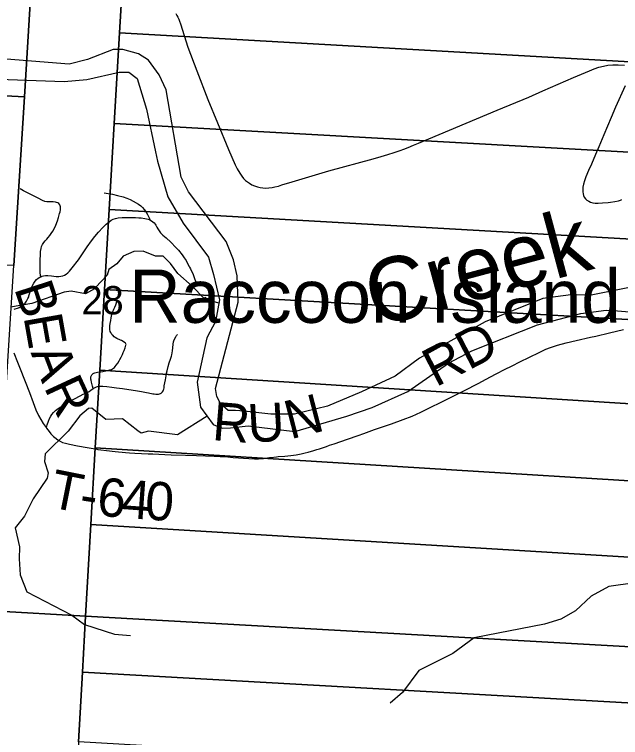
# Model space of a CAD drawing. Extents: x 396.2 to 468.4, y 232.6 to 279.1.
# Drawn here: x 422.748 to 423.645, y 273.001 to 274.071 of the extents above; entities that cross this region are included whole.
import ezdxf

# ---------------------------------------------------------------- set-up
doc = ezdxf.new("R2010")
doc.units = 0
for name, color, linetype in [('GM_X_County_Road', 7, 'Continuous'), ('GM_X_Major_River', 7, 'Continuous'), ('GM_X_Major_River_Text', 7, 'Continuous'), ('GM_X_Minor_River', 7, 'Continuous'), ('GM_X_Section', 7, 'Continuous'), ('GM_X_Section_Text', 7, 'Continuous'), ('GM_X_Township_Road', 7, 'Continuous'), ('GM_X_Township_Road_Text', 7, 'Continuous'), ('GM_X_Unincorporated_Text', 7, 'Continuous')]:
    doc.layers.add(name, color=color, linetype=linetype)

msp = doc.modelspace()

# ---------------------------------------------------------------- linework, layer by layer
at = {"layer": 'GM_X_County_Road'}
msp.add_lwpolyline([(422.9868, 274.0726), (422.9883, 274.0699), (422.9898, 274.0671), (422.991, 274.0645), (422.9922, 274.0614), (422.9935, 274.0576), (423.0046, 274.0229), (423.0175, 273.988), (423.0341, 273.9452), (423.0483, 273.9108), (423.0646, 273.8713), (423.0746, 273.8486), (423.0776, 273.8429), (423.0814, 273.8364), (423.0843, 273.8318), (423.0869, 273.8284), (423.0899, 273.8254), (423.0926, 273.8233), (423.0956, 273.8213), (423.0992, 273.8192), (423.103, 273.8176), (423.1073, 273.8161), (423.1113, 273.8151), (423.1156, 273.8144), (423.1199, 273.8142), (423.1243, 273.8144), (423.129, 273.8151), (423.1334, 273.816), (423.1385, 273.8173), (423.1436, 273.8189), (423.159, 273.8236), (423.213, 273.8396), (423.2788, 273.8574), (423.2907, 273.8608), (423.3004, 273.8638), (423.3098, 273.8668), (423.3189, 273.87), (423.3244, 273.872), (423.3306, 273.8744), (423.3387, 273.8776), (423.3461, 273.8808), (423.4622, 273.9297), (423.5091, 273.949), (423.5301, 273.9582), (423.5751, 273.9779), (423.5992, 273.9881), (423.606, 273.9909), (423.6127, 273.9933), (423.6195, 273.995), (423.6263, 273.9961), (423.6336, 273.9966), (423.6416, 273.9967), (423.651, 273.9965)], dxfattribs=at)
at = {"layer": 'GM_X_Major_River'}
for p, q in [((423.6015, 273.6556), (423.5712, 273.6562)), ((423.0513, 273.6489), (423.0454, 273.6166))]:
    msp.add_line(p, q, dxfattribs=at)
for points in [[(422.599, 274.13), (422.5858, 274.0582), (422.5866, 274.0453), (422.5951, 274.0176), (422.608, 274.0044), (422.6671, 273.9809), (422.6966, 273.9765), (422.8215, 273.9719)], [(423.5712, 273.6562), (423.53, 273.6506), (423.4444, 273.616), (423.3475, 273.5623), (423.3113, 273.5359), (423.2615, 273.5125), (423.2113, 273.4913), (423.1622, 273.4796), (423.1275, 273.4794), (423.0877, 273.4841), (423.0752, 273.4848), (423.0639, 273.4851), (423.0533, 273.4942), (423.0471, 273.5055), (423.0456, 273.5176), (423.0789, 273.6453), (423.0776, 273.6844), (423.0721, 273.7082), (423.061, 273.7351), (423.0054, 273.8088), (422.9947, 273.8303), (422.9721, 273.9595), (422.9621, 273.9819), (422.9461, 274.0038), (422.9313, 274.0128), (422.9082, 274.0195), (422.8938, 274.0194), (422.8557, 274.0048), (422.8285, 273.9978), (422.7358, 274.0052)], [(422.8215, 273.9719), (422.8551, 273.9748), (422.9027, 273.9857), (422.9171, 273.9858), (422.9296, 273.9767), (422.9431, 273.9309), (422.9563, 273.868), (422.9594, 273.854), (422.9748, 273.8014), (422.9977, 273.7624), (423.0351, 273.7118), (423.0424, 273.6861), (423.0513, 273.6489)], [(424.0857, 273.9753), (424.0692, 273.9475), (424.0531, 273.9265), (424.0445, 273.8995), (424.0269, 273.8084), (424.0187, 273.7856), (424.0044, 273.7616), (423.9626, 273.7332), (423.9158, 273.7178), (423.8274, 273.7028), (423.7817, 273.6916), (423.6015, 273.6556)], [(423.0454, 273.6166), (423.0323, 273.5927), (423.0183, 273.527), (423.023, 273.4898), (423.0421, 273.4641), (423.055, 273.4589), (423.0678, 273.4593), (423.0935, 273.4622), (423.1628, 273.4538), (423.2398, 273.4763), (423.2772, 273.4894), (423.33, 273.5132), (423.3903, 273.555), (423.4246, 273.573), (423.5219, 273.6119), (423.5861, 273.6286), (423.6239, 273.6333), (423.6345, 273.633), (423.6584, 273.6309)]]:
    msp.add_lwpolyline(points, dxfattribs=at)
at = {"layer": 'GM_X_Minor_River'}
for points in [[(423.0503, 273.6438), (423.0338, 273.6486), (423.0304, 273.6524), (423.0285, 273.6505), (423.0107, 273.669), (422.9895, 273.6876), (422.9786, 273.7028), (422.968, 273.7134), (422.9566, 273.7134), (422.9381, 273.721), (422.9245, 273.7205), (422.9086, 273.7133), (422.8992, 273.7022), (422.8875, 273.6935), (422.8852, 273.6851), (422.8678, 273.6668), (422.8663, 273.6649), (422.8527, 273.6577), (422.8319, 273.6614), (422.8213, 273.6599), (422.7734, 273.6434), (422.742, 273.638)], [(423.0329, 273.4764), (422.989, 273.4489), (422.9461, 273.4541), (422.9354, 273.4514), (422.9302, 273.4546), (422.9077, 273.4724), (422.8828, 273.4717), (422.8625, 273.4883), (422.8575, 273.4877), (422.8444, 273.4771), (422.8271, 273.4545), (422.7931, 273.4206), (422.7924, 273.4096), (422.7976, 273.3924), (422.7962, 273.3848), (422.7756, 273.3543), (422.7732, 273.3491), (422.7628, 273.3286), (422.7486, 273.3112), (422.755, 273.2832), (422.7548, 273.2654), (422.756, 273.2414), (422.7662, 273.2164), (422.8328, 273.182), (422.8516, 273.1681), (422.8958, 273.1538), (422.9195, 273.1515)], [(423.6662, 273.2298), (423.6278, 273.2242), (423.6013, 273.2099), (423.5784, 273.1882), (423.5568, 273.176), (423.5324, 273.1684), (423.4282, 273.1482), (423.3965, 273.1249), (423.3462, 273.0999), (423.3222, 273.0673), (423.304, 273.0515)]]:
    msp.add_lwpolyline(points, dxfattribs=at)
at = {"layer": 'GM_X_Section'}
for points in [[(422.7773, 274.1944), (422.7625, 273.9495), (421.7308, 274.0039), (421.7452, 274.2485)], [(422.7773, 274.1944), (422.9116, 274.1851), (422.9033, 274.0442), (422.8955, 273.9099), (422.888, 273.7823), (422.8811, 273.6643), (422.8741, 273.5445), (422.8674, 273.4297), (422.8607, 273.3162), (422.8528, 273.1802), (422.7149, 273.188), (422.7307, 273.4397), (422.7469, 273.6994), (422.7625, 273.9495)], [(422.9116, 274.1851), (423.8062, 274.1333), (423.7981, 273.9932), (422.9033, 274.0442)], [(423.7981, 273.9932), (423.7904, 273.8602), (422.8955, 273.9099), (422.9033, 274.0442)], [(421.7308, 274.0039), (422.7625, 273.9495), (422.7469, 273.6994), (421.7144, 273.7468)], [(422.8955, 273.9099), (423.7904, 273.8602), (423.7829, 273.7317), (422.888, 273.7823)], [(423.7829, 273.7317), (423.776, 273.6125), (422.8811, 273.6643), (422.888, 273.7823)], [(422.8811, 273.6643), (423.776, 273.6125), (423.7688, 273.4879), (422.8741, 273.5445)], [(423.7688, 273.4879), (423.7622, 273.3741), (422.8674, 273.4297), (422.8741, 273.5445)], [(422.8674, 273.4297), (423.7622, 273.3741), (423.7556, 273.2617), (422.8607, 273.3162)], [(423.7556, 273.2617), (423.748, 273.13), (422.8528, 273.1802), (422.8607, 273.3162)], [(422.8528, 273.1802), (422.8483, 273.0976), (422.8427, 272.9941), (422.8371, 272.89), (422.8314, 272.7848), (422.8262, 272.6889), (422.8208, 272.5886), (422.8152, 272.4837), (422.8095, 272.3782), (422.8042, 272.2802), (422.7982, 272.1692), (422.6516, 272.1773), (422.6675, 272.4285), (422.6838, 272.6898), (422.6989, 272.9313), (422.7149, 273.188)], [(423.748, 273.13), (423.7432, 273.047), (422.8483, 273.0976), (422.8528, 273.1802)], [(423.7432, 273.047), (423.7371, 272.9426), (422.8427, 272.9941), (422.8483, 273.0976)]]:
    msp.add_lwpolyline(points, close=True, dxfattribs=at)
at = {"layer": 'GM_X_Township_Road'}
for points in [[(423.6516, 273.9658), (423.6377, 273.9343), (423.6312, 273.9189), (423.6204, 273.8933), (423.613, 273.8755), (423.608, 273.8641), (423.6018, 273.8499), (423.5975, 273.8403), (423.5938, 273.831), (423.5917, 273.8252), (423.5901, 273.8198), (423.5892, 273.8155), (423.5889, 273.8118), (423.5889, 273.8087), (423.5894, 273.8056), (423.5901, 273.8033), (423.5911, 273.801), (423.5929, 273.7985), (423.5952, 273.7964), (423.5978, 273.7948), (423.6007, 273.7935), (423.6037, 273.7926), (423.6073, 273.7921), (423.6117, 273.7919), (423.6185, 273.7923), (423.6266, 273.7931), (423.6303, 273.7935), (423.6364, 273.7943), (423.6419, 273.7954), (423.6448, 273.7964), (423.647, 273.7975)], [(422.7867, 273.683), (422.786, 273.6884), (422.7856, 273.695), (422.7856, 273.7031), (422.7865, 273.7205), (422.7871, 273.7248), (422.7879, 273.7277), (422.7892, 273.7306), (422.7912, 273.7337), (422.7931, 273.736), (422.7955, 273.7387), (422.7978, 273.7412), (422.8002, 273.7441), (422.8021, 273.7468), (422.8044, 273.7502), (422.8063, 273.754), (422.8088, 273.7592), (422.8113, 273.7658), (422.8131, 273.7707), (422.8146, 273.7765), (422.8152, 273.7791), (422.8159, 273.7821), (422.8161, 273.7846), (422.816, 273.7865), (422.8154, 273.7882), (422.8149, 273.7893), (422.8133, 273.7912), (422.8118, 273.7922), (422.8101, 273.793), (422.8083, 273.7934), (422.8052, 273.7937), (422.8023, 273.7937), (422.7989, 273.7937), (422.7958, 273.794), (422.7928, 273.7946), (422.7893, 273.7959), (422.7826, 273.7992), (422.771, 273.8051), (422.7611, 273.8104), (422.756, 273.8129)], [(422.8804, 273.8071), (422.8835, 273.8067), (422.8927, 273.805), (422.9005, 273.8033), (422.9089, 273.8012), (422.9143, 273.7995), (422.9188, 273.7975), (422.9237, 273.7949), (422.9312, 273.7904), (422.9348, 273.7879), (422.9375, 273.7854), (422.9399, 273.7826), (422.9421, 273.7796), (422.9445, 273.7753), (422.9463, 273.772), (422.9475, 273.7692), (422.9483, 273.7671)], [(422.7471, 273.6349), (422.7538, 273.6369), (422.7549, 273.6373), (422.7574, 273.6389), (422.7584, 273.6395), (422.7603, 273.6411), (422.7621, 273.6427), (422.7634, 273.644), (422.7656, 273.6469), (422.7662, 273.6479), (422.7676, 273.6506), (422.7688, 273.6534), (422.7692, 273.6546), (422.7701, 273.6575), (422.7716, 273.6622), (422.7731, 273.6668), (422.7746, 273.6702), (422.7763, 273.6733), (422.7783, 273.6764), (422.7804, 273.6787), (422.7827, 273.6807), (422.7853, 273.6823), (422.7867, 273.683), (422.7881, 273.6837), (422.7905, 273.6844), (422.7935, 273.6849), (422.7973, 273.6849), (422.8028, 273.6843), (422.8095, 273.6835), (422.8132, 273.6834), (422.8163, 273.6837), (422.8193, 273.6844), (422.8216, 273.6853), (422.8243, 273.6869), (422.8267, 273.6888), (422.8294, 273.6914), (422.8334, 273.6962), (422.8425, 273.7079), (422.8467, 273.714), (422.8552, 273.727), (422.8616, 273.7361), (422.8666, 273.7425), (422.8722, 273.7491), (422.8786, 273.7559), (422.8834, 273.7607), (422.8874, 273.764), (422.8909, 273.7667), (422.8939, 273.7681), (422.8973, 273.7692), (422.9011, 273.77), (422.907, 273.7705), (422.9146, 273.7706), (422.9216, 273.7706), (422.927, 273.7707), (422.9319, 273.7704), (422.9355, 273.77), (422.9409, 273.7691), (422.9457, 273.768), (422.9483, 273.7671), (422.9508, 273.7659), (422.9528, 273.7645), (422.9545, 273.7627), (422.9559, 273.7609), (422.9569, 273.7591), (422.9583, 273.7566), (422.9599, 273.7539), (422.9618, 273.7511), (422.9641, 273.7482), (422.9675, 273.7446), (422.9721, 273.7404), (422.979, 273.7342), (422.9868, 273.7264), (422.9908, 273.7221), (422.996, 273.7152), (422.999, 273.7111), (423.0017, 273.707), (423.0035, 273.7037), (423.0066, 273.6983), (423.0071, 273.6973), (423.0084, 273.6947), (423.0121, 273.6865), (423.0139, 273.6817), (423.0162, 273.6751)], [(422.8645, 273.5175), (422.8635, 273.5208), (422.8618, 273.5267), (422.8612, 273.5297), (422.8609, 273.5315), (422.8607, 273.5326), (422.8607, 273.5338), (422.8608, 273.5348), (422.8611, 273.5357), (422.8616, 273.5368), (422.8623, 273.5376), (422.8629, 273.5383), (422.8636, 273.539), (422.8645, 273.5397), (422.8654, 273.5402), (422.8666, 273.5407), (422.8686, 273.5411), (422.8705, 273.5414), (422.8737, 273.5419), (422.8786, 273.5426), (422.8829, 273.5435), (422.886, 273.5441), (422.8888, 273.5449), (422.8912, 273.5458), (422.893, 273.5467), (422.8942, 273.5474), (422.8956, 273.5485), (422.8969, 273.5499), (422.8985, 273.5519), (422.9008, 273.5551), (422.9026, 273.5582), (422.9039, 273.5605), (422.9056, 273.564), (422.9075, 273.5677), (422.9089, 273.5706), (422.9102, 273.5738), (422.9118, 273.5779), (422.9123, 273.5796), (422.9128, 273.5818), (422.9129, 273.5827), (422.9126, 273.5836), (422.912, 273.5845), (422.9107, 273.5857), (422.9086, 273.5871), (422.9064, 273.5883), (422.9047, 273.589), (422.9025, 273.59), (422.9014, 273.5905), (422.8993, 273.5916), (422.8969, 273.5932), (422.8954, 273.5942), (422.8932, 273.5962), (422.8924, 273.5971), (422.8917, 273.5979), (422.891, 273.5989), (422.8902, 273.6004), (422.8896, 273.6019), (422.8889, 273.6047), (422.8889, 273.607), (422.8891, 273.6101), (422.8896, 273.6138), (422.8902, 273.6181), (422.8909, 273.6223), (422.892, 273.6269), (422.8933, 273.6308), (422.8948, 273.6347), (422.8962, 273.6381), (422.8978, 273.6415), (422.8989, 273.6444), (422.8995, 273.6467), (422.8998, 273.6479)], [(422.8696, 273.4275), (422.8713, 273.4273), (422.8756, 273.4267), (422.8842, 273.4256), (422.897, 273.4242), (422.9121, 273.4228), (422.9181, 273.4224), (422.9259, 273.4219), (422.9456, 273.4209), (422.9524, 273.4206), (422.9617, 273.4202), (422.9704, 273.4198), (422.9796, 273.4193), (423.0007, 273.4185), (423.0174, 273.4181), (423.0432, 273.4173), (423.0524, 273.4169), (423.0634, 273.4161), (423.0714, 273.4154), (423.0794, 273.4147), (423.0868, 273.4141), (423.0949, 273.4136), (423.1029, 273.4133), (423.109, 273.4134), (423.1163, 273.414), (423.1251, 273.4152), (423.1274, 273.4155), (423.1358, 273.4165), (423.1382, 273.4167), (423.1481, 273.4175), (423.1524, 273.4178), (423.1567, 273.4183), (423.1647, 273.419), (423.172, 273.4205), (423.178, 273.422), (423.1826, 273.4232), (423.1911, 273.4257), (423.1955, 273.427), (423.1994, 273.4283), (423.2039, 273.4297), (423.2096, 273.4316), (423.2141, 273.4333), (423.2211, 273.4356), (423.241, 273.4422), (423.2568, 273.448), (423.2649, 273.451), (423.2808, 273.4567), (423.3059, 273.4652), (423.3234, 273.4714), (423.3367, 273.4767), (423.3492, 273.4823), (423.3652, 273.4902), (423.3776, 273.4963), (423.3865, 273.5006), (423.4131, 273.5141), (423.4351, 273.5256), (423.445, 273.5307), (423.4609, 273.5393), (423.4742, 273.546), (423.4837, 273.5506), (423.497, 273.5573), (423.5093, 273.5634), (423.5254, 273.5715), (423.5344, 273.5756), (423.5414, 273.5782), (423.5514, 273.5815), (423.5646, 273.5852), (423.5791, 273.5887), (423.6003, 273.5933), (423.6082, 273.5951), (423.6287, 273.6001), (423.6493, 273.6048)], [(422.7946, 273.4595), (422.7958, 273.4615), (422.7964, 273.4637), (422.7981, 273.469), (422.7998, 273.473), (422.8014, 273.4763), (422.8031, 273.4789), (422.8054, 273.4818), (422.8085, 273.4849), (422.8123, 273.488), (422.8202, 273.493), (422.8287, 273.4981), (422.8365, 273.5022), (422.8452, 273.5067), (422.8496, 273.5089), (422.8542, 273.5109), (422.8584, 273.5132), (422.8608, 273.515), (422.8645, 273.5175), (422.867, 273.5191), (422.8693, 273.52), (422.8723, 273.5208), (422.8746, 273.521), (422.8787, 273.5209), (422.8843, 273.5204), (422.8917, 273.5195), (422.899, 273.5185), (422.9076, 273.5173), (422.9107, 273.5169), (422.9205, 273.5154), (422.9297, 273.514), (422.9358, 273.513), (422.9431, 273.5117), (422.946, 273.511), (422.9528, 273.5097), (422.9545, 273.5094), (422.9572, 273.509), (422.9587, 273.5089), (422.9603, 273.509), (422.9612, 273.5091), (422.9626, 273.5094), (422.9639, 273.51), (422.9649, 273.5106), (422.9661, 273.5115), (422.9671, 273.5127), (422.9678, 273.5139), (422.9683, 273.5153), (422.9687, 273.5163), (422.9692, 273.5184), (422.9696, 273.5213), (422.9711, 273.5301), (422.9716, 273.5331), (422.9722, 273.536), (422.973, 273.5401), (422.9738, 273.5436), (422.9754, 273.5501), (422.977, 273.5555), (422.9788, 273.5607), (422.9804, 273.5653), (422.9808, 273.5671), (422.9819, 273.573), (422.9823, 273.5778), (422.9827, 273.5832), (422.9834, 273.5868), (422.9844, 273.5897), (422.9865, 273.5941), (422.9874, 273.5957), (422.9889, 273.5976)], [(422.7469, 273.5701), (422.7523, 273.5566), (422.7563, 273.5464), (422.7701, 273.5117), (422.7755, 273.4965), (422.7796, 273.4861), (422.7834, 273.4776), (422.7866, 273.4716), (422.7901, 273.4657), (422.7946, 273.4595), (422.7952, 273.4586), (422.799, 273.4538), (422.8018, 273.4505), (422.8057, 273.4465), (422.8095, 273.4433), (422.8125, 273.4411), (422.8152, 273.4395), (422.8191, 273.4377), (422.8233, 273.4364), (422.8293, 273.4349), (422.8409, 273.4326), (422.8552, 273.4301), (422.867, 273.4279), (422.8696, 273.4275)]]:
    msp.add_lwpolyline(points, dxfattribs=at)

# ---------------------------------------------------------------- texts
at = {"layer": 'GM_X_Major_River_Text'}
msp.add_text('Creek', height=0.09469, rotation=14.9998, dxfattribs=at).set_placement((423.2819, 273.6077))
at = {"layer": 'GM_X_Section_Text'}
msp.add_text('28', height=0.04186, rotation=0, dxfattribs=at).set_placement((422.8471, 273.6273))
at = {"layer": 'GM_X_Township_Road_Text'}
for s, height, rotation, p in [('B', 0.0568, 288.0968, (422.747, 273.666)), ('E', 0.0568, 280.0193, (422.761, 273.6237)), ('RD', 0.05682, 27.407, (423.3714, 273.5188)), ('A', 0.0568, 290.6476, (422.7714, 273.5708)), ('R', 0.0568, 294.8309, (422.7908, 273.5198)), ('N', 0.0568, 14.4269, (423.156, 273.442)), ('R', 0.0568, 355.3757, (423.0394, 273.4412)), ('U', 0.0568, 3.1865, (423.0942, 273.4373)), ('T', 0.0568, 348.6048, (422.7973, 273.3424)), ('6', 0.0568, 354.6585, (422.8685, 273.3296)), ('4', 0.0568, 355.9016, (422.9047, 273.3262)), ('0', 0.0568, 356.0397, (422.9397, 273.3237)), ('-', 0.0568, 351.4113, (422.8419, 273.3335))]:
    msp.add_text(s, height=height, rotation=rotation, dxfattribs=at).set_placement(p)
at = {"layer": 'GM_X_Unincorporated_Text'}
msp.add_text('Raccoon Island', height=0.078977, rotation=0, dxfattribs=at).set_placement((422.9175, 273.6147))

doc.saveas('drawing.dxf')
